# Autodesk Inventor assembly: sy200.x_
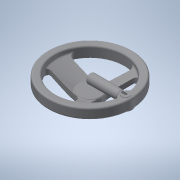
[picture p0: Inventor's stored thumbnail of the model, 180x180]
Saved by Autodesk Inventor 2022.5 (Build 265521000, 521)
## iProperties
Part Number: sy200.x_
Material: 一般
Document SubType Name: Assembly
Designer: ImaoCorp
Sending System: SOLIDWORKS 2017-2017317
MC: AMD64
MC_MODEL: Intel64 Family 6 Model 60 Stepping 3, GenuineIntel
OS: Windows_NT
FRU: Parasolid Version 29.0, build 201,  4-17-2017
FORMAT: text
GUISE: transmit
KEY: sy200
FILE: sy200.x_t
DATE: Wed Sep 18 16:02:19 2019
Author: ImaoCorp
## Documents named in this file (3)
- X:\14_SW2022-Inv2022\00_全2023-1023新製品(TCC)まで\s\sy200\SY200.iam
- X:\14_SW2022-Inv2022\00_全2023-1023新製品(TCC)まで\s\sy200\sy200_01.ipt
- X:\14_SW2022-Inv2022\00_全2023-1023新製品(TCC)まで\s\sy200\sy200_02.ipt
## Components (2 placed, 2 different names)
1. sy200_01
2. sy200_02
